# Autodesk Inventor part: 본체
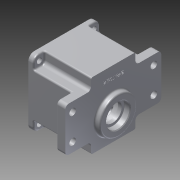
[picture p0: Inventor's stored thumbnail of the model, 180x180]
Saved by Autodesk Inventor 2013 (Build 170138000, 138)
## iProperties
Created: 2015-07
Part Number: 본체
Material: 알루미늄 6061
Document SubType Name: Modeling
Designer: user
Density: 2.71 g/cm^3
Mass: 705.341 g
Surface Area: 672.954 cm^2
Volume: 260.274 cm^3
Author: user
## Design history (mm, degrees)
sketch "스케치1"
  geometry: L1 (-65, -30)-(65, -30); L2 (65, -30)-(65, 30); L3 (65, 30)-(-65, 30); L4 (-65, 30)-(-65, -30); 3 further points
  constraints: 8 end point, 2 midpoint, 2 parallel, 1 horizontal, 1 horizontal alignment, 1 perpendicular, 1 vertical alignment
  dimensions: "d0" = 130 distance of L3.end L2.end; "d1" = 60 distance of L2.end L1.end
extrude "돌출1" new body sketch "스케치1" distance "d2" = 12; taper "d3" = 0 deg
fillet "모깎기1" dims "d4" = 5
sketch "스케치2"
  geometry: L1 (25, 65)-(-25, 65) reference; L2 (0, 0)-(0, -55); L3 (0, -55)-(-17.5, -55); L4 (0, -55)-(17.5, -55); L5 (0, 0)-(13, 0); C1 r 4.5 at (-17.5, -55); C2 r 4.5 at (17.5, -55); C3 r 4.5 at (-17.5, 55); C4 r 4.5 at (17.5, 55)
  constraints: 8 end point, 4 centre point, 2 coincident, 2 perpendicular, 2 symmetric about line, 1 collinear, 1 parallel, 2 other
  dimensions: "d5" = 55 distance of L2.start L2.end; "d6" = 17.5 distance of L2.end L3.end; "d7" = 9 diameter of C1; "d8" = 17.5 distance of L2.end L4.end; "d9" = 9 diameter of C2
extrude "돌출2" cut sketch "스케치2" distance "d10" = 12; taper "d11" = 0 deg
sketch "스케치3"
  geometry: L1 (30, -45)-(-30, -45); L2 (-30, -45)-(-30, 45); L3 (-30, 45)-(30, 45); L4 (30, 45)-(30, -45); 3 further points
  constraints: 8 end point, 2 midpoint, 2 parallel, 1 horizontal, 1 horizontal alignment, 1 perpendicular, 1 vertical alignment
  dimensions: "d12" = 60 distance of L2.end L3.end; "d13" = 90 distance of L1.end L2.end
extrude "돌출3" join sketch "스케치3" distance "d14" = 51; taper "d15" = 0 deg
sketch "스케치4"
  geometry: L1 (45, -45)-(-45, -45); L2 (-45, -45)-(-45, 45); L3 (-45, 45)-(45, 45); L4 (45, 45)-(45, -45); 3 further points
  constraints: 8 end point, 2 midpoint, 2 parallel, 1 horizontal, 1 horizontal alignment, 1 perpendicular, 1 vertical alignment
  dimensions: "d16" = 90 distance of L2.end L3.end; "d17" = 90 distance of L1.end L2.end
extrude "돌출4" join sketch "스케치4" distance "d18" = 7; taper "d19" = 0 deg
sketch "스케치5"
  geometry: L1 (30, -60)-(30, 60) reference; L2 (0, 0)-(30, 0); L3 (30, 0)-(30, 30); L4 (30, 0)-(30, -30); L5 (45, -45)-(45, 45) reference; L6 (-30, -45)-(-30, 45) reference; L7 (-30, 45)-(-45, 45) reference; L8 (-45, 45)-(-45, -45) reference; L9 (-45, -45)-(-30, -45) reference; L10 (30, 45)-(30, -45) reference; L11 (30, -45)-(45, -45) reference; L12 (45, -45)-(45, 45) reference; L13 (45, 45)-(30, 45) reference; L14 (30, 30)-(45, 30); L15 (45, 30)-(45, -30); L16 (30, -30)-(45, -30); L17 (0, 0)-(0, -15); L18 (-30, -30)-(-45, -30); L19 (-45, 30)-(-45, -30); L20 (-30, 30)-(-30, -30); L21 (-30, 30)-(-45, 30)
  constraints: 22 end point, 4 point on line, 4 symmetric about line, 3 perpendicular, 1 midpoint
  dimensions: "d20" = 30 distance of L2.end L3.end; "d21" = 30 distance of L2.end L4.end
extrude "돌출5" join sketch "스케치5" stored distance "d22" = 7; taper "d23" = 0 deg
sketch "스케치7"
  geometry: C1 r 40 at (0, 0); 1 further point
  constraints: 1 centre point, 1 coincident
  dimensions: "d27" = 80 diameter of C1
extrude "돌출7" cut sketch "스케치7" distance "d28" = 9; taper "d29" = 0 deg
sketch "스케치10"
  geometry: C1 r 40 at (0, 0) reference; C2 r 39 at (0, 0)
  constraints: 1 centre point, 1 coincident
  dimensions: "d36" = 78 diameter of C2
extrude "돌출10" cut sketch "스케치10" distance "d37" = 52; taper "d38" = 0 deg
sketch "스케치11"
  geometry: L1 (30, 60)-(30, 30) reference; L2 (30, 30)-(45, 30) reference; L3 (45, 30)-(45, -30) reference; L4 (45, -30)-(30, -30) reference; L5 (30, -30)-(30, -60) reference; L6 (25, -65)-(-25, -65) reference; L7 (-30, -60)-(-30, -30) reference; L8 (-30, -30)-(-45, -30) reference; L9 (-45, -30)-(-45, 30) reference; L10 (-45, 30)-(-30, 30) reference; L11 (-30, 30)-(-30, 60) reference; L12 (-25, 65)-(25, 65) reference; L13 (0, 0)-(-11, 0); L14 (0, 0)-(20, 0); C1 r 39 at (0, 0) reference; C2 r 4.5 at (17.5, 55) reference; C3 r 4.5 at (17.5, -55) reference; C4 r 4.5 at (-17.5, -55) reference; C5 r 4.5 at (-17.5, 55) reference; A1 r 5 centre (25, 60) between (30, 60) and (25, 65) reference; A2 r 5 centre (25, -60) between (25, -65) and (30, -60) reference; A3 r 5 centre (-25, -60) between (-30, -60) and (-25, -65) reference; A4 r 5 centre (-25, 60) between (-25, 65) and (-30, 60) reference; A5 r 20.5 centre (-11, 0) between (8.117, 7.402) and (8.117, -7.402); A6 r 14 centre (20, 0) between (8.117, -7.402) and (8.117, 7.402)
  constraints: 4 end point, 4 point on circle, 2 centre point, 2 coincident, 1 collinear, 1 parallel
  dimensions: "d39" = 11 distance of L13.start L13.end; "d42" = 20 distance of L13.start L14.end; "d44" = 41 diameter of A5; "d45" = 28 diameter of A6
extrude "돌출11" join sketch "스케치11" distance "d46" = 7; taper "d47" = 0 deg
sketch "스케치12"
  geometry: C1 r 17.5 at (-11, 0); C2 r 11 at (20, 0); A1 r 20.5 centre (-11, 0) between (8.117, 7.402) and (8.117, -7.402) reference; A2 r 14 centre (20, 0) between (8.117, -7.402) and (8.117, 7.402) reference; 1 further point
  constraints: 2 centre point, 2 coincident
  dimensions: "d48" = 35 diameter of C1; "d49" = 22 diameter of C2
extrude "돌출12" cut sketch "스케치12" distance "d50" = 10; taper "d51" = 0 deg
extrude "돌출13" cut sketch "스케치12" distance "d52" = 7; taper "d53" = 0 deg
sketch "스케치13"
  geometry: C1 r 11 at (0, 0) reference; C2 r 9.5 at (0, 0); 1 further point
  constraints: 1 centre point, 1 coincident
  dimensions: "d54" = 19 diameter of C2
extrude "돌출14" cut sketch "스케치13" distance "d55" = 1; taper "d56" = 0 deg
fillet "모깎기2" dims "d57" = 3
fillet "모깎기3" dims "d58" = 2
sketch "스케치14"
  geometry: L1 (30, -60)-(30, -30) reference; L2 (0, 0)-(11, 0); C1 r 25 at (11, 0)
  constraints: 2 end point, 1 centre point, 1 coincident, 1 perpendicular
  dimensions: "d59" = 11 distance of L2.start L2.end; "d60" = 50 diameter of C1
extrude "돌출15" join sketch "스케치14" distance "d61" = 7; taper "d62" = 0 deg
sketch "스케치15"
  geometry: C1 r 25 at (0, 0) reference; C2 r 16 at (0, 0); 1 further point
  constraints: 1 centre point, 1 coincident
  dimensions: "d63" = 32 diameter of C2
extrude "돌출16" cut sketch "스케치15" distance "d64" = 8; taper "d65" = 0 deg
sketch "스케치16"
  geometry: C1 r 16 at (0, 0) reference; C2 r 12.5 at (0, 0); 1 further point
  constraints: 1 centre point, 1 coincident
  dimensions: "d66" = 25 diameter of C2
extrude "돌출17" cut sketch "스케치16" distance "d67" = 5; taper "d68" = 0 deg
sketch "스케치17"
  geometry: L1 (0, 0)-(-35, 0); L2 (0, 0)-(24.749, 24.749); L3 (0, 0)-(35, 0); A1 r 39 centre (0, 0) between (32.777, 21.134) and (21.134, 32.777) reference; A2 r 35 centre (0, 0) between (21.763, 27.411) and (27.411, 21.763); A3 r 4 centre (24.749, 24.749) between (21.809, 27.462) and (27.462, 21.809); A4 r 3.5 centre (29.836, 19.238) between (32.777, 21.134) and (27.412, 21.762); A5 r 3.5 centre (19.238, 29.836) between (21.762, 27.412) and (21.134, 32.777)
  constraints: 17 point on circle, 6 end point, 4 centre point, 4 tangent, 2 coincident, 2 horizontal, 1 equal length
  dimensions: "d69" = 70 diameter of A2; "d70" = 45 deg angle of L3 L2; "d71" = 8 diameter of A3; "d72" = 7 diameter of A4; "d73" = 7 diameter of A5; "d74" = 5.35816 distance of A3.end A1.start
extrude "돌출18" join sketch "스케치17" distance "d75" = 52; taper "d76" = 0 deg
sketch "스케치18"
  geometry: A1 r 4 centre (24.749, -24.749) between (27.462, -21.809) and (21.809, -27.462) reference; A2 r 4 centre (-24.749, -24.749) between (-21.809, -27.462) and (-27.462, -21.809) reference; A3 r 4 centre (-24.749, 24.749) between (-27.462, 21.809) and (-21.809, 27.462) reference; A4 r 4 centre (24.749, 24.749) between (21.809, 27.462) and (27.462, 21.809) reference; 4 further points
  constraints: 4 coincident
hole "구멍1" sketch "스케치18" at (-24.749, -24.749), (-24.749, 24.749), (24.749, -24.749), (24.749, 24.749) diameter "d80" = 3.459; stored, may be unused: countersink angle "d84" = 90 deg, drill point angle "d86" = 118 deg; dims "d81" = 12, "d82" = 4, "d83" = 2, "d85" = 15
fillet "모깎기4" dims "d87" = 2
fillet "모깎기5" dims "d88" = 2
fillet "모깎기6" dims "d89" = 8
fillet "모깎기7" dims "d90" = 5
fillet "모깎기8" dims "d91" = 2
fillet "모깎기9" dims "d92" = 2
sketch "스케치19"
  geometry: L1 (-45, -28)-(-45, 28) reference; L2 (-43, 30)-(-35, 30) reference; L3 (-45, 0)-(-30, 0); 2 further points
  constraints: 2 end point, 1 coincident, 1 midpoint, 1 parallel, 1 other
  dimensions: "d93" = 15 distance of L3.start L3.end
feature "엠보싱1" sketch "스케치19" dims "d5" = 55, "d6" = 17.5, "d7" = 9, "d8" = 17.5, "d9" = 9, "d94" = 0.5, "d95" = 0
fillet "모깎기10" dims "d96" = 0.3
chamfer "모따기1" distance "d97" = 1; stored, may be unused: second distance "d98" = 2, angle "d99" = 45 deg
fillet "모깎기11" dims "d100" = 0.3
chamfer "모따기2" distance "d101" = 1; stored, may be unused: second distance "d102" = 2, angle "d103" = 45 deg
fillet "모깎기12" dims "d104" = 2
fillet "모깎기13" dims "d105" = 2
sketch "스케치20"
  geometry: L1 (45, -37)-(45, 37) reference; L2 (0, 0)-(0, -11.542); C1 r 40 at (0, 0) reference; C2 r 3.5 at (-37, 37); C3 r 3.5 at (-37, -37); C4 r 3.5 at (37, 37); C5 r 3.5 at (37, -37); A1 r 8 centre (-37, 37) between (-37, 45) and (-45, 37) reference; A2 r 8 centre (-37, -37) between (-45, -37) and (-37, -45) reference
  constraints: 4 centre point, 2 coincident, 2 end point, 2 symmetric about line, 1 parallel, 2 other
  dimensions: "d106" = 7 diameter of C2; "d107" = 7 diameter of C3
extrude "돌출19" cut sketch "스케치20" distance "d108" = 10; taper "d109" = 0 deg
fillet "모깎기14" dims "d110" = 2
node "솔리드1"
pattern_circular "원형 패턴1" dims angle "d78" = 360 deg
node "투영된 루프1"
node "투영된 루프2"
node "절단 모서리 투영1"
